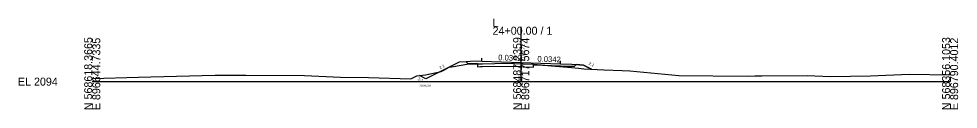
# Model space of a CAD drawing. Extents: x -26 to 1603, y -10 to 13527.
# Drawn here: x -25.7 to 302.8, y 11490.3 to 11522 of the extents above; entities that cross this region are included whole.
import ezdxf

# ---------------------------------------------------------------- set-up
doc = ezdxf.new("R2010")
doc.units = 0
for name, color, linetype in [('Default', 7, 'Continuous'), ('Exist XS Center Line Elevation Label', 7, 'Continuous'), ('Exist XS Ground Line', 7, 'Continuous'), ('Old_Level_61', 7, 'Continuous'), ('Old_Level_63', 7, 'Continuous'), ('Prop XS Ditch Standard Text', 7, 'Continuous'), ('Prop XS Earthwork Shape', 7, 'Continuous'), ('Prop XS EOT Tick Mark', 7, 'Continuous'), ('Prop XS Finish Grade', 7, 'Continuous'), ('Prop XS Finish Grade Earthwork', 7, 'Continuous'), ('Prop XS Finish Grade Paved Shoulder', 7, 'Continuous'), ('Prop XS Finish Grade Pavement', 7, 'Continuous'), ('Prop XS Side Slope Text', 7, 'Continuous'), ('Prop XS Subgrade Earthwork', 7, 'Continuous'), ('Prop XSC Text', 7, 'Continuous')]:
    doc.layers.add(name, color=color, linetype=linetype)

msp = doc.modelspace()

# ---------------------------------------------------------------- linework, layer by layer
at = {"layer": 'Exist XS Ground Line'}
for p, q in [((125.58, 11505.2), (131.71, 11506.18)), ((131.71, 11506.18), (133.85, 11506.19)), ((133.85, 11506.19), (134.78, 11506.23)), ((134.78, 11506.23), (136.53, 11506.26)), ((136.53, 11506.26), (145.07, 11506.42)), ((145.07, 11506.42), (150, 11506.25)), ((150, 11506.25), (150.73, 11506.22)), ((150.73, 11506.22), (154.34, 11506.09)), ((154.34, 11506.09), (167.59, 11504.95)), ((20.44, 11501.7), (43.02, 11502.27)), ((43.02, 11502.27), (48.13, 11502.31)), ((48.13, 11502.31), (53.74, 11502.28)), ((53.74, 11502.28), (74.27, 11502.1)), ((74.27, 11502.1), (86.78, 11501.58)), ((111.37, 11500.97), (113.51, 11501.99)), ((113.51, 11501.99), (116.59, 11502.39)), ((116.59, 11502.39), (122.05, 11503.5)), ((122.05, 11503.5), (122.98, 11503.99)), ((122.98, 11503.99), (124.87, 11505.02)), ((124.87, 11505.02), (125.24, 11505.15)), ((125.24, 11505.15), (125.58, 11505.2)), ((167.59, 11504.95), (170.04, 11504.71)), ((170.04, 11504.71), (171.89, 11504.53)), ((171.89, 11504.53), (178.96, 11504.19)), ((178.96, 11504.19), (185.33, 11503.95)), ((185.33, 11503.95), (187.97, 11503.82)), ((187.97, 11503.82), (205.16, 11502.15)), ((205.16, 11502.15), (229.06, 11501.96)), ((229.06, 11501.96), (231.69, 11502.01)), ((231.69, 11502.01), (234.14, 11502)), ((234.14, 11502), (250.02, 11502.14)), ((250.02, 11502.14), (258.16, 11501.77)), ((258.16, 11501.77), (272.19, 11502.03)), ((272.19, 11502.03), (285.67, 11502.56)), ((285.67, 11502.56), (300, 11502.4)), ((0, 11501.08), (16.22, 11501.57)), ((16.22, 11501.57), (20.44, 11501.7)), ((86.78, 11501.58), (96.6, 11501.5)), ((96.6, 11501.5), (111.37, 11500.97))]:
    msp.add_line(p, q, dxfattribs=at)
at = {"layer": 'Old_Level_61'}
for p, q in [((134.78, 11506.23), (134.78, 11505.23)), ((134.78, 11505.23), (135.79, 11505.25)), ((135.79, 11505.25), (136.53, 11505.26)), ((136.53, 11505.26), (145.07, 11505.42)), ((145.07, 11505.42), (150, 11505.25)), ((150, 11505.25), (150.73, 11505.22)), ((150.73, 11505.22), (154.34, 11505.09)), ((154.34, 11505.09), (154.34, 11506.09))]:
    msp.add_line(p, q, dxfattribs=at)
at = {"layer": 'Old_Level_63'}
for p, q in [((150, 11500), (150, 11519.25)), ((0, 11500), (150, 11500)), ((150, 11500), (300, 11500))]:
    msp.add_line(p, q, dxfattribs=at)
at = {"layer": 'Prop XS Earthwork Shape'}
for points in [[(131.44, 11506.29), (130.74, 11506.98), (128.28, 11506.78), (121.5, 11503.39), (122.05, 11503.5), (122.98, 11503.99), (124.87, 11505.02), (125.24, 11505.15), (125.58, 11505.2), (131.71, 11506.18), (133.85, 11506.19), (134.78, 11506.23), (134.78, 11506.36)], [(154.34, 11505.77), (154.34, 11506.09), (160.57, 11505.56)], [(171.89, 11504.53), (174.54, 11504.41), (171.78, 11505.78), (169.28, 11505.98), (168.58, 11505.28), (163.71, 11505.45), (160.57, 11505.56), (167.59, 11504.95), (170.04, 11504.71)], [(114.44, 11502.11), (116.59, 11502.39), (121.5, 11503.39), (116.71, 11501)]]:
    msp.add_lwpolyline(points, close=True, dxfattribs=at)
at = {"layer": 'Prop XS EOT Tick Mark'}
for p, q in [((136.28, 11507.18), (136.28, 11508.18)), ((163.71, 11506.24), (163.71, 11507.24))]:
    msp.add_line(p, q, dxfattribs=at)
at = {"layer": 'Prop XS Finish Grade'}
for p, q in [((132.25, 11507.1), (130.74, 11506.98)), ((167.75, 11506.1), (169.28, 11505.98))]:
    msp.add_line(p, q, dxfattribs=at)
at = {"layer": 'Prop XS Finish Grade Earthwork'}
for p, q in [((128.28, 11506.78), (116.71, 11501)), ((130.74, 11506.98), (128.28, 11506.78)), ((169.28, 11505.98), (171.78, 11505.78)), ((171.78, 11505.78), (174.54, 11504.41)), ((116.71, 11501), (114.44, 11502.11))]:
    msp.add_line(p, q, dxfattribs=at)
at = {"layer": 'Prop XS Finish Grade Paved Shoulder'}
for p, q in [((136.28, 11507.18), (132.25, 11507.1)), ((163.71, 11506.24), (167.75, 11506.1))]:
    msp.add_line(p, q, dxfattribs=at)
at = {"layer": 'Prop XS Finish Grade Pavement'}
for p, q in [((136.28, 11507.18), (150, 11506.71)), ((150, 11506.71), (163.71, 11506.24))]:
    msp.add_line(p, q, dxfattribs=at)
at = {"layer": 'Prop XS Subgrade Earthwork'}
for p, q in [((131.44, 11506.29), (130.74, 11506.98)), ((134.78, 11506.36), (131.44, 11506.29)), ((134.78, 11506.36), (134.78, 11506.23)), ((154.34, 11505.77), (154.34, 11506.09)), ((163.71, 11505.45), (154.34, 11505.77)), ((163.71, 11505.45), (168.58, 11505.28)), ((168.58, 11505.28), (169.28, 11505.98))]:
    msp.add_line(p, q, dxfattribs=at)

# ---------------------------------------------------------------- texts
at = {"layer": 'Default'}
for p in [(141.94, 11507.49), (155.65, 11507.02)]:
    msp.add_text('0.0342', height=2, rotation=358.0396, dxfattribs=at).set_placement(p)
at = {"layer": 'Exist XS Center Line Elevation Label'}
msp.add_text('2100.25', height=1, rotation=90, dxfattribs=at).set_placement((150.5, 11498.68))
at = {"layer": 'Old_Level_63'}
for s, p in [('L', (140, 11519.25)), ('24+00.00 / 1', (140, 11516.45)), ('EL 2094', (-26, 11498.6))]:
    msp.add_text(s, height=2.8, dxfattribs=at).set_placement(p)
for s, p in [('N 568618.3665', (0, 11490)), ('E 896644.7335', (2.8, 11490)), ('N 568487.2359', (150, 11490)), ('E 896717.5674', (152.8, 11490)), ('N 568356.1053', (300, 11490)), ('E 896790.4012', (302.8, 11490))]:
    msp.add_text(s, height=2.8, rotation=90, dxfattribs=at).set_placement(p)
at = {"layer": 'Prop XS Ditch Standard Text'}
msp.add_text('2095.00', height=0.8, dxfattribs=at).set_placement((114.44, 11498.18))
at = {"layer": 'Prop XS Side Slope Text'}
for rotation, p in [(25.9715, (121.67, 11504.34)), (333.4349, (173.51, 11506.04)), (334.0285, (113.71, 11500.63))]:
    msp.add_text('2:1', height=1, rotation=rotation, dxfattribs=at).set_placement(p)
at = {"layer": 'Prop XSC Text'}
msp.add_text(' 2100.71', height=1.2, rotation=90, dxfattribs=at).set_placement((151.2, 11506.71))

doc.saveas('drawing.dxf')
